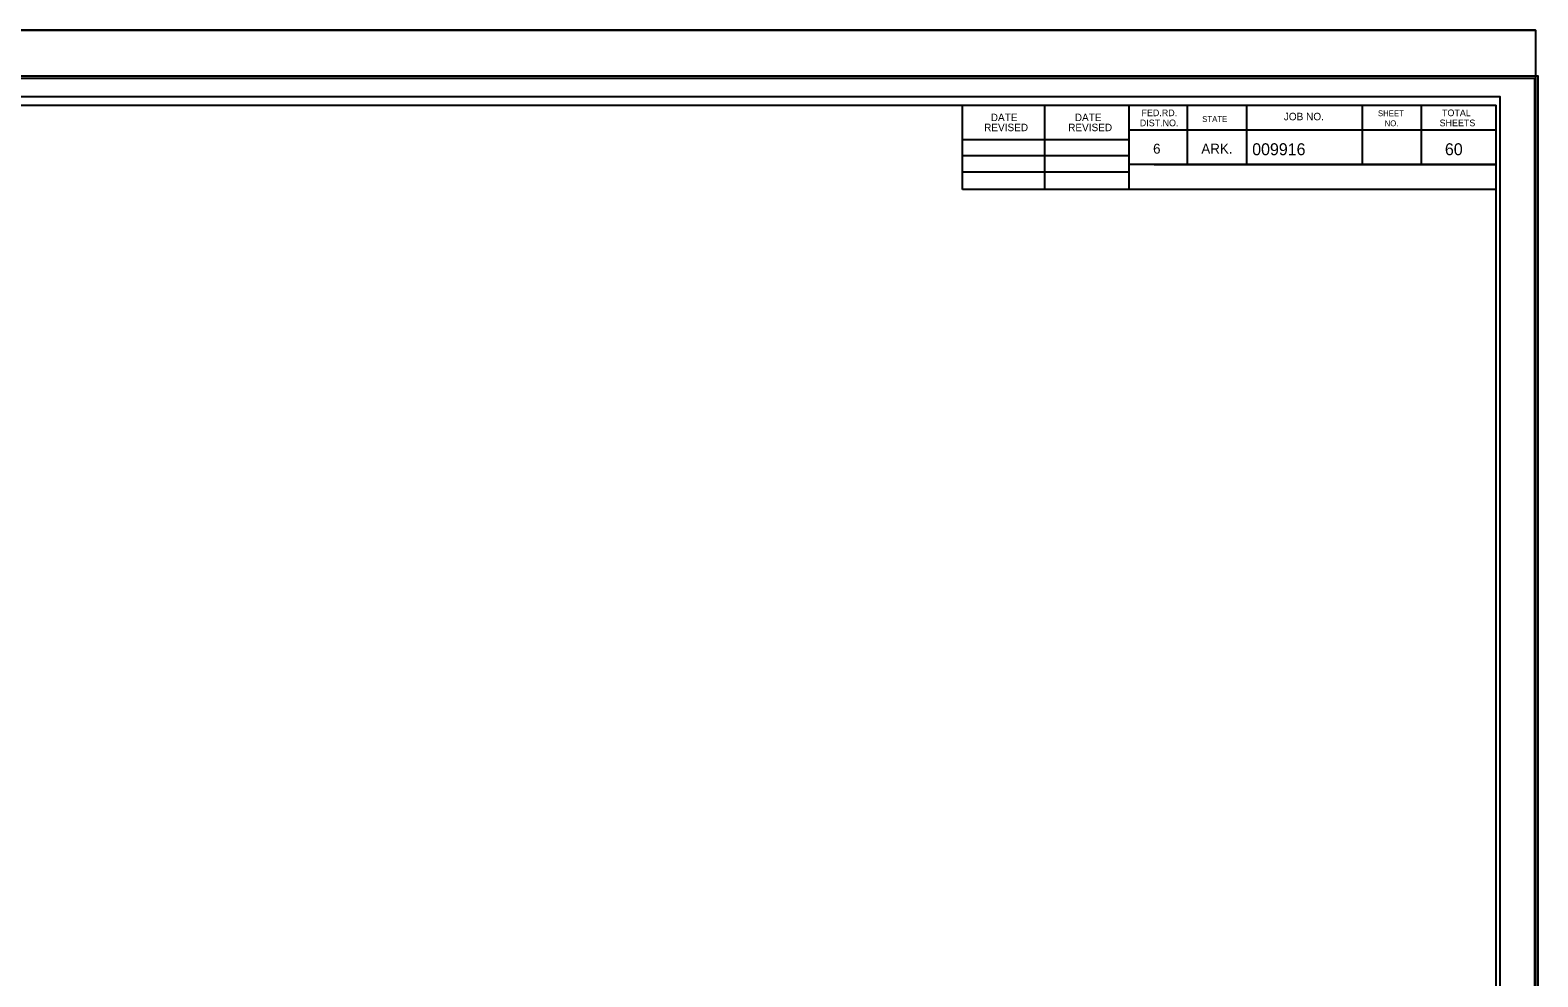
# Model space of a CAD drawing. Extents: x 1376650 to 1380188, y 377544 to 379765.
# Drawn here: x 1378419 to 1380188, y 378655 to 379765 of the extents above; entities that cross this region are included whole.
import ezdxf

# ---------------------------------------------------------------- set-up
doc = ezdxf.new("R2010")
doc.units = 0
for name, color, linetype in [('Level 1', 7, 'Continuous'), ('Level 62', 7, 'Continuous'), ('Plot_Normal', 7, 'Continuous'), ('Plot_PDF', 7, 'Continuous'), ('R_Border', 7, 'Continuous'), ('R_No Plot', 7, 'Continuous')]:
    doc.layers.add(name, color=color, linetype=linetype)

msp = doc.modelspace()

# ---------------------------------------------------------------- linework, layer by layer
at = {"layer": 'Level 1'}
for p in [(1376938.5, 379677.3), (1380139.6, 377622.7)]:
    msp.add_line(p, (1380139.6, 379677.3), dxfattribs=at)
at = {"layer": 'Level 62'}
msp.add_lwpolyline([(1376850.1, 379709.2), (1380184.6, 379709.2), (1380184.6, 377600), (1376850.1, 377600)], close=True, dxfattribs=at)
at = {"layer": 'Plot_Normal'}
msp.add_lwpolyline([(1376853.9, 379712), (1380188.4, 379712), (1380188.4, 377588), (1376853.9, 377588)], close=True, dxfattribs=at)
at = {"layer": 'Plot_PDF'}
msp.add_lwpolyline([(1376848.7, 377594), (1380144.1, 377594), (1380144.1, 379687.4), (1376848.7, 379687.4)], close=True, dxfattribs=at)
at = {"layer": 'R_Border'}
for p, q in [((1380185.8, 379765.5), (1376650.4, 379765.5)), ((1379513.2, 379578.5), (1379513.2, 379677.3)), ((1379610, 379578.5), (1379610, 379677.3)), ((1379708.6, 379677.3), (1379708.6, 379578.5)), ((1379777, 379677.3), (1379777, 379607.9)), ((1379846.4, 379677.3), (1379846.4, 379607.9)), ((1379982.2, 379677.3), (1379982.2, 379607.9)), ((1380051.6, 379677.3), (1380051.6, 379607.9)), ((1379513.2, 379637.1), (1379708.6, 379637.1)), ((1380139.6, 379647.9), (1379708.6, 379647.9)), ((1380139.6, 379648.1), (1380139.6, 379648.1)), ((1379513.2, 379618.5), (1379708.6, 379618.5)), ((1379513.2, 379599.1), (1379708.6, 379599.1)), ((1380139.6, 379607.9), (1379708.6, 379607.9)), ((1379738.2, 379607.9), (1380139.6, 379607.9)), ((1380139.6, 379578.5), (1379513.2, 379578.5))]:
    msp.add_line(p, q, dxfattribs=at)
at = {"layer": 'R_No Plot'}
for points in [[(1376650.4, 379765.5), (1380185.8, 379765.5), (1380185.8, 377543.6), (1376650.4, 377543.6)], [(1376850.1, 379709.2), (1380184.6, 379709.2), (1380184.6, 377600), (1376850.1, 377600)]]:
    msp.add_lwpolyline(points, close=True, dxfattribs=at)

# ---------------------------------------------------------------- texts
at = {"layer": 'R_Border'}
for s, height, p in [('FED.RD.', 7.82, (1379723.4, 379664.5)), ('JOB NO.', 8.79, (1379890.4, 379659.7)), ('SHEET', 6.84, (1380000.8, 379664.5)), ('TOTAL', 7.82, (1380076, 379664.5)), ('REVISED', 8.79, (1379538.7, 379646.9)), ('DATE', 8.79, (1379546.5, 379658.7)), ('REVISED', 8.79, (1379637.3, 379646.9)), ('DATE', 8.79, (1379645.1, 379658.7)), ('DIST.NO.', 7.82, (1379721.4, 379652.7)), ('STATE', 6.84, (1379794.6, 379657.7)), ('NO.', 6.84, (1380008.6, 379652.7)), ('SHEETS', 7.82, (1380073.2, 379652.7)), ('009916', 14, (1379853.3, 379618.7)), ('60', 14, (1380079.4, 379618.7)), ('6', 11.7, (1379737, 379620.5)), ('ARK.', 11.72, (1379793.6, 379620.5))]:
    msp.add_text(s, height=height, dxfattribs=at).set_placement(p)

doc.saveas('drawing.dxf')
